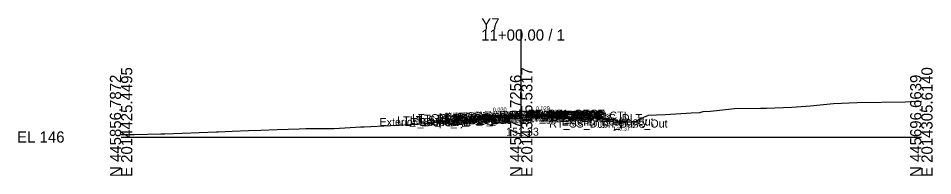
# Model space of a CAD drawing. Extents: x -26 to 203, y -10 to 7527.
# Drawn here: x -25.7 to 202.8, y 1990.3 to 2029.7 of the extents above; entities that cross this region are included whole.
import ezdxf

# ---------------------------------------------------------------- set-up
doc = ezdxf.new("R2010")
doc.units = 0
for name, color, linetype in [('Exist CMT Pavement', 7, 'Continuous'), ('Exist Cross Section Cell', 7, 'Continuous'), ('Exist XS Center Line Elevation Label', 7, 'Continuous'), ('Exist XS Ground Line', 7, 'Continuous'), ('Prop CMT Pvmt Course 1', 7, 'Continuous'), ('Prop CMT Pvmt Course 1 Wedge', 7, 'Continuous'), ('Prop CMT Pvmt Course 2', 7, 'Continuous'), ('Prop CMT Pvmt Course 2 Wedge', 7, 'Continuous'), ('Prop CMT Pvmt Course 3', 7, 'Continuous'), ('Prop CMT Pvmt Course 3 Wedge', 7, 'Continuous'), ('Prop CMT Pvmt Surface', 7, 'Continuous'), ('Prop CMT Pvmt Surface Shoulder', 7, 'Continuous'), ('Prop CMT Pvmt Wedge Surface 1', 7, 'Continuous'), ('Prop CMT Pvmt Wedge Surface 2', 7, 'Continuous'), ('Prop CMT Pvmt Wedge Surface 3', 7, 'Continuous'), ('Prop CMT Shld Paved Course 1', 7, 'Continuous'), ('Prop CMT Shld Paved Course 2', 7, 'Continuous'), ('Prop CMT Shld Paved Course 3', 7, 'Continuous'), ('Prop CMT Slope Grass', 7, 'Continuous'), ('Prop CMT Subgrade Earthwork', 7, 'Continuous'), ('Prop XS Ditch Standard Text', 7, 'Continuous'), ('Prop XS Earthwork Shape', 7, 'Continuous'), ('Prop XS SE Text', 7, 'Continuous'), ('Prop XS Side Slope Text', 7, 'Continuous'), ('Scratch_Level_0', 7, 'Continuous')]:
    doc.layers.add(name, color=color, linetype=linetype)

msp = doc.modelspace()

# ---------------------------------------------------------------- linework, layer by layer
at = {"layer": 'Exist CMT Pavement'}
for points in [[(93.54, 2005.07), (100, 2005.33), (100.85, 2005.36), (101.26, 2005.38), (107.3, 2005.4), (107.61, 2005.4), (107.61, 2005.4)], [(93.54, 2005.07), (100, 2005.33)]]:
    msp.add_lwpolyline(points, dxfattribs=at)
at = {"layer": 'Exist Cross Section Cell'}
for p, q in [((100, 2000), (100, 2026.94)), ((0, 2000), (100, 2000)), ((100, 2000), (200, 2000))]:
    msp.add_line(p, q, dxfattribs=at)
at = {"layer": 'Exist XS Ground Line'}
msp.add_lwpolyline([(0, 2000.62), (3.27, 2000.64), (9.91, 2000.8), (10.89, 2000.79), (23.84, 2001.27), (24.29, 2001.28), (27.79, 2001.5), (31.85, 2001.61), (34.89, 2001.71), (39, 2001.92), (44.48, 2002.07), (46.14, 2002.17), (47.38, 2002.13), (53.29, 2002.17), (59.88, 2002.52), (60.78, 2002.54), (73.9, 2003.23), (74.23, 2003.23), (77.87, 2003.6), (81.87, 2003.84), (91.61, 2004.81), (93.54, 2005.07), (100, 2005.33), (100.85, 2005.36), (101.26, 2005.38), (107.3, 2005.4), (107.61, 2005.4), (112.07, 2006.1), (113.73, 2006.43), (115.37, 2005.98), (117.66, 2005.18), (118.48, 2005.04), (123.53, 2004.19), (124.27, 2003.82), (126.05, 2003.88), (128.18, 2003.7), (130.02, 2004.76), (131.83, 2005.49), (133.78, 2005.53), (136.02, 2005.66), (142.44, 2006.07), (144.63, 2006.12), (145.45, 2006.41), (147.32, 2006.51), (153.31, 2007.14), (159.81, 2007.19), (160.46, 2007.22), (161.32, 2007.22), (167.6, 2007.46), (172.3, 2007.83), (174.75, 2008.07), (178.01, 2008.41), (183.97, 2008.67), (196.02, 2008.8), (197.29, 2008.91), (200, 2008.98)], dxfattribs=at)
at = {"layer": 'Prop CMT Pvmt Course 1'}
for points in [[(100, 2005.54), (89.39, 2005.22)], [(89.39, 2005.22), (89.39, 2004.97)], [(89.39, 2004.97), (93.54, 2005.09)], [(93.54, 2005.22), (100, 2005.41)], [(93.54, 2005.09), (93.54, 2005.22)], [(100, 2005.54), (110.96, 2005.85)], [(107.61, 2005.63), (100, 2005.41)], [(100, 2005.29), (100, 2005.54)], [(100, 2005.29), (100, 2005.54)], [(100, 2005.41), (100, 2005.29), (100, 2005.29)], [(100, 2005.41), (100, 2005.29), (100, 2005.29)], [(107.61, 2005.5), (107.61, 2005.63)], [(110.96, 2005.6), (107.61, 2005.5)], [(110.96, 2005.85), (110.96, 2005.6)]]:
    msp.add_lwpolyline(points, dxfattribs=at)
at = {"layer": 'Prop CMT Pvmt Course 1 Wedge'}
for points in [[(100, 2005.41), (93.54, 2005.22)], [(100, 2005.41), (107.61, 2005.63)]]:
    msp.add_lwpolyline(points, dxfattribs=at)
at = {"layer": 'Prop CMT Pvmt Course 2'}
for points in [[(93.54, 2005.09), (89.39, 2004.97)], [(89.39, 2004.97), (89.39, 2004.63)], [(89.39, 2004.63), (93.54, 2004.76)], [(93.54, 2004.76), (93.54, 2005.09)], [(107.61, 2005.5), (110.96, 2005.6)], [(107.61, 2005.17), (107.61, 2005.5)], [(110.96, 2005.27), (107.61, 2005.17)], [(110.96, 2005.6), (110.96, 2005.27)]]:
    msp.add_lwpolyline(points, dxfattribs=at)
at = {"layer": 'Prop CMT Pvmt Course 2 Wedge'}
for points in [[(100, 2005.29), (93.54, 2005.09)], [(100, 2005.29), (107.61, 2005.5)]]:
    msp.add_lwpolyline(points, dxfattribs=at)
at = {"layer": 'Prop CMT Pvmt Course 3'}
for points in [[(93.54, 2004.76), (89.39, 2004.63)], [(89.39, 2004.63), (89.39, 2004.3)], [(89.39, 2004.3), (93.54, 2004.43)], [(93.54, 2004.43), (93.54, 2004.76)], [(107.61, 2005.17), (110.96, 2005.27)], [(107.61, 2004.84), (107.61, 2005.17)], [(110.96, 2004.93), (107.61, 2004.84)], [(110.96, 2005.27), (110.96, 2004.93)]]:
    msp.add_lwpolyline(points, dxfattribs=at)
at = {"layer": 'Prop CMT Pvmt Course 3 Wedge'}
for points in [[(100, 2004.95), (93.54, 2004.76)], [(100, 2004.95), (107.61, 2005.17)]]:
    msp.add_lwpolyline(points, dxfattribs=at)
at = {"layer": 'Prop CMT Pvmt Surface'}
for points in [[(100, 2005.54), (89.39, 2005.22)], [(100, 2005.54), (110.96, 2005.85)]]:
    msp.add_lwpolyline(points, dxfattribs=at)
at = {"layer": 'Prop CMT Pvmt Surface Shoulder'}
for points in [[(89.39, 2005.22), (89.39, 2005.22)], [(110.96, 2005.85), (110.96, 2005.85)]]:
    msp.add_lwpolyline(points, dxfattribs=at)
at = {"layer": 'Prop CMT Pvmt Wedge Surface 1'}
for points in [[(89.39, 2004.97), (89.39, 2005.22)], [(93.54, 2005.09), (89.39, 2004.97)], [(100, 2005.41), (93.54, 2005.22)], [(93.54, 2005.22), (93.54, 2005.09)], [(100, 2005.41), (107.61, 2005.63)], [(107.61, 2005.63), (107.61, 2005.5)], [(107.61, 2005.5), (110.96, 2005.6)], [(110.96, 2005.6), (110.96, 2005.85)]]:
    msp.add_lwpolyline(points, dxfattribs=at)
at = {"layer": 'Prop CMT Pvmt Wedge Surface 2'}
for points in [[(100, 2005.29), (89.39, 2004.97)], [(89.39, 2004.97), (89.39, 2005.22)], [(100, 2005.29), (110.96, 2005.6)], [(110.96, 2005.6), (110.96, 2005.85)]]:
    msp.add_lwpolyline(points, dxfattribs=at)
at = {"layer": 'Prop CMT Pvmt Wedge Surface 3'}
for points in [[(89.39, 2004.63), (89.39, 2005.22)], [(100, 2004.95), (89.39, 2004.63)], [(100, 2004.95), (110.96, 2005.27)], [(110.96, 2005.27), (110.96, 2005.85)]]:
    msp.add_lwpolyline(points, dxfattribs=at)
at = {"layer": 'Prop CMT Shld Paved Course 1'}
for points in [[(89.39, 2005.22), (89.14, 2004.96)], [(89.14, 2004.96), (89.39, 2004.97)], [(89.39, 2005.22), (89.39, 2005.22)], [(89.39, 2004.97), (89.39, 2005.22)], [(110.96, 2005.85), (110.96, 2005.85)], [(110.96, 2005.85), (111.21, 2005.59)], [(110.96, 2005.6), (110.96, 2005.85)], [(111.21, 2005.59), (110.96, 2005.6)]]:
    msp.add_lwpolyline(points, dxfattribs=at)
at = {"layer": 'Prop CMT Shld Paved Course 2'}
for points in [[(89.39, 2004.97), (89.14, 2004.96), (88.8, 2004.62)], [(88.8, 2004.62), (89.39, 2004.63)], [(89.39, 2004.63), (89.39, 2004.97)], [(110.96, 2005.6), (111.21, 2005.59), (111.55, 2005.25)], [(110.96, 2005.27), (110.96, 2005.6)], [(111.55, 2005.25), (110.96, 2005.27)]]:
    msp.add_lwpolyline(points, dxfattribs=at)
at = {"layer": 'Prop CMT Shld Paved Course 3'}
for points in [[(87.96, 2004.27), (89.39, 2004.3)], [(89.39, 2004.63), (88.8, 2004.62), (88.46, 2004.28)], [(89.39, 2004.3), (89.39, 2004.63)], [(110.96, 2004.93), (110.96, 2005.27)], [(110.96, 2005.27), (111.55, 2005.25), (111.89, 2004.91)], [(112.39, 2004.9), (110.96, 2004.93)]]:
    msp.add_lwpolyline(points, dxfattribs=at)
at = {"layer": 'Prop CMT Slope Grass'}
for points in [[(89.39, 2005.22), (83.39, 2004.74), (80.45, 2003.76)], [(110.96, 2005.85), (116.96, 2005.37), (124.96, 2003.37), (126.41, 2003.85)]]:
    msp.add_lwpolyline(points, dxfattribs=at)
at = {"layer": 'Prop CMT Subgrade Earthwork'}
for points in [[(87.96, 2004.27), (81.61, 2004.15)], [(89.39, 2004.3), (87.96, 2004.27)], [(93.54, 2004.43), (89.39, 2004.3)], [(93.54, 2004.43), (93.54, 2005.07)], [(107.61, 2004.84), (107.61, 2005.4)], [(107.61, 2004.84), (110.96, 2004.93)], [(110.96, 2004.93), (112.39, 2004.9)], [(112.39, 2004.9), (119.38, 2004.76)]]:
    msp.add_lwpolyline(points, dxfattribs=at)
at = {"layer": 'Prop XS Earthwork Shape'}
for points in [[(93.54, 2004.43), (89.39, 2004.3), (87.96, 2004.27), (85.75, 2004.23), (91.61, 2004.81), (93.54, 2005.07)], [(110.34, 2005.83), (110.96, 2005.85), (116.96, 2005.37), (117.51, 2005.23), (117.66, 2005.18), (117.84, 2005.15), (119.38, 2004.76), (112.39, 2004.9), (110.96, 2004.93), (107.61, 2004.84), (107.61, 2005.4)], [(110.34, 2005.83), (110.96, 2005.85), (116.96, 2005.37), (117.51, 2005.23), (115.37, 2005.98), (113.73, 2006.43), (112.07, 2006.1)], [(124.96, 2003.37), (126.41, 2003.85), (126.05, 2003.88), (124.27, 2003.82), (123.53, 2004.19), (118.48, 2005.04), (117.84, 2005.15), (119.38, 2004.76)], [(85.75, 2004.23), (81.61, 2004.15), (80.45, 2003.76), (81.87, 2003.84)]]:
    msp.add_lwpolyline(points, close=True, dxfattribs=at)

# ---------------------------------------------------------------- texts
at = {"layer": 'Exist Cross Section Cell'}
for s, p in [('Y7', (90, 2026.94)), ('11+00.00 / 1', (90, 2024.14)), ('EL 146', (-26, 1998.6))]:
    msp.add_text(s, height=2.8, dxfattribs=at).set_placement(p)
for s, p in [('E 2014425.4495', (2.8, 1990)), ('E 2014365.5317', (102.8, 1990)), ('E 2014305.6140', (202.8, 1990)), ('N 445856.7872', (0, 1990)), ('N 445776.7256', (100, 1990)), ('N 445696.6639', (200, 1990))]:
    msp.add_text(s, height=2.8, rotation=90, dxfattribs=at).set_placement(p)
at = {"layer": 'Exist XS Center Line Elevation Label'}
msp.add_text('151.33', height=2, dxfattribs=at).set_placement((96.23, 2000.33))
at = {"layer": 'Prop XS Ditch Standard Text'}
msp.add_text('149.37', height=1, dxfattribs=at).set_placement((122.93, 2001.62))
at = {"layer": 'Prop XS SE Text'}
for s, rotation, p in [('0.030', 1.7184, (92.92, 2006.32)), ('0.029', 1.6336, (103.71, 2006.64))]:
    msp.add_text(s, height=1, rotation=rotation, dxfattribs=at).set_placement(p)
at = {"layer": 'Prop XS Side Slope Text'}
for s, rotation, p in [('3:1', 18.4332, (80.93, 2004.71)), ('4:1', 345.9638, (120.37, 2005.29)), ('3:1', 18.4349, (124.8, 2003.94))]:
    msp.add_text(s, height=1, rotation=rotation, dxfattribs=at).set_placement(p)
at = {"layer": 'Scratch_Level_0'}
for s, p in [('PV1_PGL', (94.47, 2004.54)), ('RT_PV2_OEEOP', (96.87, 2004.5)), ('RT_PV1_OEEOP', (97.44, 2004.63)), ('RT_PV2_OEOT', (101.08, 2004.6)), ('RT_PS2_OEOP', (101.4, 2004.59)), ('RT_PV1_OEOT', (101.65, 2004.85)), ('RT_PS1_OEOP', (101.71, 2004.85)), ('Exterior Boundary', (64.59, 2002.76)), ('LT_Sub_OSS_DLT', (69.02, 2003.15)), ('LT_Slope_Fill', (70.97, 2002.76)), ('LT_Sub_Trench_Out', (72.16, 2003.27)), ('LT_GS_OS_CTL', (72.76, 2003.74)), ('LT_PS3_Shelf_Out', (74.28, 2003.61)), ('LT_PS3_OEOP', (79.03, 2003.62)), ('LT_PS2_OEOP', (79.37, 2003.96)), ('LT_Sub_OEOT', (79.47, 2003.3)), ('LT_PV2_OEOT', (79.56, 2003.97)), ('LT_PV3_OEOT', (79.56, 2003.63)), ('LT_PV1_OEOT', (80.13, 2004.22)), ('LT_PS1_OEOP', (80.19, 2004.22)), ('LT_Sub Tie Out', (80.88, 2004.07)), ('LT_PV_OEEOP_EG', (81.08, 2004.07)), ('LT_Sub_OEEOP', (82.75, 2003.43)), ('LT_PV2_OEEOP', (82.84, 2004.09)), ('LT_PV3_OEEOP', (82.84, 2003.76)), ('LT_PV1_OEEOP', (83.41, 2004.22)), ('RT_PV_IEEOP_EG', (88.14, 2004.33)), ('LT_PV_IEEOP_EG', (88.19, 2004.33)), ('RT_PV2_IEEOP', (89.91, 2004.29)), ('RT_PV3_IEEOP', (89.91, 2003.95)), ('LT_PV2_IEEOP', (89.95, 2004.29)), ('LT_PV3_IEEOP', (89.95, 2003.95)), ('RT_PV1_IEEOP', (90.47, 2004.41)), ('LT_PV1_IEEOP', (90.52, 2004.41)), ('PV2_PGL', (93.91, 2004.29)), ('RT_Sub Tie Out', (94.9, 2004.4)), ('RT_PV_OEEOP_EG', (95.1, 2004.4)), ('RT_Sub_Trench_Out', (96.55, 2003.9)), ('RT_Sub_OEEOP', (96.77, 2003.84)), ('RT_PV3_OEEOP', (96.87, 2004.17)), ('RT_PS3_Shelf_Out', (97.99, 2004.24)), ('RT_Sub_OEOT', (100.99, 2003.93)), ('RT_PV3_OEOT', (101.08, 2004.27)), ('RT_PS3_OEOP', (101.74, 2004.25)), ('RT_GS_OS_CTL', (106.28, 2004.37)), ('RT_Sub_OSS_DLT', (106.73, 2003.76)), ('RT_SS_Ditch_Base_Out', (106.99, 2002.37)), ('Exterior Boundary', (110.12, 2002.88)), ('RT_Slope_Cut', (115.57, 2002.88))]:
    msp.add_text(s, height=2, dxfattribs=at).set_placement(p)

doc.saveas('drawing.dxf')
